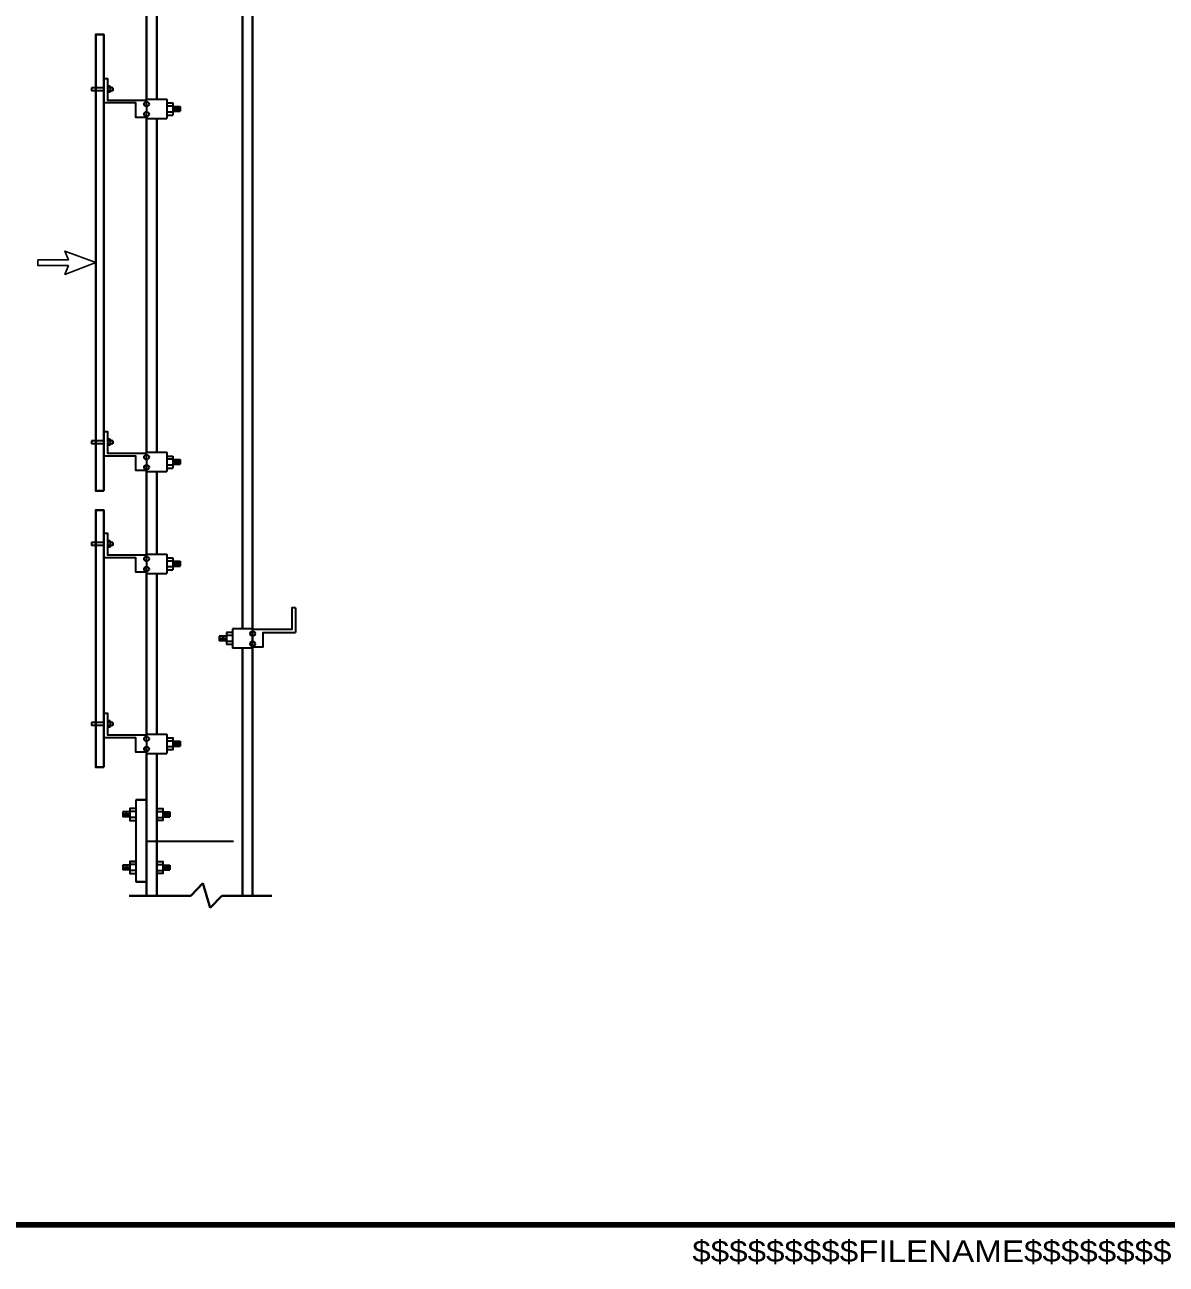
# Model space of a CAD drawing. Extents: x 851 to 1706, y -23 to 521.
# Drawn here: x 1358.6 to 1475.1, y -15.9 to 110.6 of the extents above; entities that cross this region are included whole.
import ezdxf

# ---------------------------------------------------------------- set-up
doc = ezdxf.new("R2010")
doc.units = 0
doc.header["$PDMODE"] = 32
doc.header["$PDSIZE"] = 0.5
doc.layers.add('1', color=7, linetype='Continuous', lineweight=35)

msp = doc.modelspace()

# ---------------------------------------------------------------- linework, layer by layer
at = {"layer": '1', "lineweight": 40}
for p, q in [((1381.875, 128.673), (1381.875, 21.729)), ((1380.841, 119.132), (1380.841, 48.984)), ((1371.049, 112.954), (1371.049, 103.03)), ((1372.082, 112.954), (1372.082, 103.03)), ((1371.049, 101.062), (1371.049, 66.999)), ((1372.082, 101.062), (1372.082, 66.999)), ((1371.049, 65.031), (1371.049, 56.611)), ((1372.082, 65.031), (1372.082, 56.611)), ((1371.049, 54.643), (1371.049, 38.241)), ((1372.082, 54.643), (1372.082, 38.241)), ((1380.841, 47.016), (1380.841, 21.729)), ((1371.049, 21.729), (1371.049, 36.272)), ((1372.082, 21.729), (1372.082, 36.272)), ((1371.049, 31.516), (1369.966, 31.516)), ((1371.049, 23.15), (1369.966, 23.15)), ((1376.79, 23.014), (1375.576, 21.729)), ((1376.79, 23.014), (1377.544, 20.498)), ((1369.278, 21.729), (1375.576, 21.729)), ((1378.726, 21.729), (1377.544, 20.498)), ((1378.726, 21.729), (1383.843, 21.729))]:
    msp.add_line(p, q, dxfattribs=at)
at = {"layer": '1'}
for p, q in [((1366.686, 105.163), (1366.686, 102.648)), ((1365.425, 104.206), (1365.425, 103.905)), ((1366.686, 104.206), (1365.425, 104.206)), ((1366.686, 103.905), (1365.425, 103.905)), ((1367.342, 104.37), (1367.047, 104.37)), ((1367.604, 104.206), (1367.047, 104.206)), ((1367.604, 103.905), (1367.047, 103.905)), ((1367.342, 103.741), (1367.047, 103.741)), ((1367.342, 104.37), (1367.342, 103.741)), ((1367.604, 104.206), (1367.604, 103.905)), ((1371.049, 103.03), (1373.116, 103.03)), ((1371.049, 102.347), (1371.049, 103.03)), ((1373.116, 103.03), (1373.116, 101.062)), ((1373.116, 102.648), (1373.726, 102.648)), ((1373.726, 102.648), (1373.726, 101.418)), ((1371.049, 102.347), (1371.049, 101.746)), ((1371.049, 101.308), (1371.049, 101.746)), ((1371.049, 101.308), (1371.049, 101.062)), ((1373.116, 102.347), (1373.726, 102.347)), ((1373.116, 101.746), (1373.726, 101.746)), ((1373.116, 101.418), (1373.726, 101.418)), ((1373.726, 102.292), (1374.461, 102.292)), ((1373.726, 101.8), (1374.461, 101.8)), ((1373.918, 102.156), (1373.918, 101.91)), ((1374.097, 102.292), (1374.097, 101.8)), ((1374.297, 102.156), (1374.297, 101.91)), ((1374.461, 102.292), (1374.461, 101.8)), ((1371.049, 101.062), (1373.116, 101.062)), ((1366.686, 69.132), (1366.686, 66.617)), ((1367.342, 68.339), (1367.047, 68.339)), ((1367.342, 68.339), (1367.342, 67.71)), ((1365.425, 68.175), (1365.425, 67.874)), ((1366.686, 68.175), (1365.425, 68.175)), ((1366.686, 67.874), (1365.425, 67.874)), ((1367.604, 68.175), (1367.047, 68.175)), ((1367.604, 67.874), (1367.047, 67.874)), ((1367.342, 67.71), (1367.047, 67.71)), ((1367.604, 68.175), (1367.604, 67.874)), ((1371.049, 67), (1373.116, 67)), ((1371.049, 66.316), (1371.049, 67)), ((1371.049, 66.316), (1371.049, 65.715)), ((1373.116, 67), (1373.116, 65.031)), ((1373.116, 66.617), (1373.726, 66.617)), ((1373.116, 66.316), (1373.726, 66.316)), ((1373.726, 66.617), (1373.726, 65.387)), ((1373.726, 66.261), (1374.461, 66.261)), ((1373.918, 66.125), (1373.918, 65.879)), ((1374.097, 66.261), (1374.097, 65.769)), ((1374.297, 66.125), (1374.297, 65.879)), ((1374.461, 66.261), (1374.461, 65.769)), ((1371.049, 65.277), (1371.049, 65.715)), ((1371.049, 65.277), (1371.049, 65.031)), ((1371.049, 65.031), (1373.116, 65.031)), ((1373.116, 65.715), (1373.726, 65.715)), ((1373.116, 65.387), (1373.726, 65.387)), ((1373.726, 65.769), (1374.461, 65.769)), ((1366.686, 58.744), (1366.686, 56.229)), ((1365.425, 57.787), (1365.425, 57.486)), ((1366.686, 57.787), (1365.425, 57.787)), ((1366.686, 57.486), (1365.425, 57.486)), ((1367.342, 57.951), (1367.047, 57.951)), ((1367.604, 57.787), (1367.047, 57.787)), ((1367.604, 57.486), (1367.047, 57.486)), ((1367.342, 57.322), (1367.047, 57.322)), ((1367.342, 57.951), (1367.342, 57.322)), ((1367.604, 57.787), (1367.604, 57.486)), ((1371.049, 56.611), (1373.116, 56.611)), ((1371.049, 55.928), (1371.049, 56.611)), ((1371.049, 55.928), (1371.049, 55.327)), ((1373.116, 56.611), (1373.116, 54.643)), ((1373.116, 56.229), (1373.726, 56.229)), ((1373.116, 55.928), (1373.726, 55.928)), ((1373.726, 56.229), (1373.726, 54.998)), ((1373.726, 55.873), (1374.461, 55.873)), ((1373.918, 55.736), (1373.918, 55.491)), ((1374.097, 55.873), (1374.097, 55.381)), ((1374.297, 55.736), (1374.297, 55.491)), ((1374.461, 55.873), (1374.461, 55.381)), ((1371.049, 54.889), (1371.049, 55.327)), ((1371.049, 54.889), (1371.049, 54.643)), ((1371.049, 54.643), (1373.116, 54.643)), ((1373.116, 55.327), (1373.726, 55.327)), ((1373.116, 54.998), (1373.726, 54.998)), ((1373.726, 55.381), (1374.461, 55.381)), ((1386.238, 51.116), (1386.238, 48.601)), ((1379.197, 48.246), (1378.463, 48.246)), ((1378.463, 48.246), (1378.463, 47.754)), ((1378.627, 48.109), (1378.627, 47.863)), ((1378.827, 48.246), (1378.827, 47.754)), ((1379.005, 48.109), (1379.005, 47.863)), ((1379.808, 48.601), (1379.197, 48.601)), ((1379.197, 48.601), (1379.197, 47.371)), ((1379.808, 48.301), (1379.197, 48.301)), ((1381.875, 48.984), (1379.808, 48.984)), ((1379.808, 48.984), (1379.808, 47.016)), ((1381.875, 48.301), (1381.875, 48.984)), ((1381.875, 48.301), (1381.875, 47.699)), ((1379.197, 47.754), (1378.463, 47.754)), ((1379.808, 47.699), (1379.197, 47.699)), ((1379.808, 47.371), (1379.197, 47.371)), ((1381.875, 47.016), (1379.808, 47.016)), ((1381.875, 47.262), (1381.875, 47.699)), ((1381.875, 47.262), (1381.875, 47.016)), ((1365.425, 39.416), (1365.425, 39.115)), ((1366.686, 39.416), (1365.425, 39.416)), ((1366.686, 40.373), (1366.686, 37.858)), ((1367.342, 39.58), (1367.047, 39.58)), ((1367.604, 39.416), (1367.047, 39.416)), ((1367.342, 39.58), (1367.342, 38.951)), ((1367.604, 39.416), (1367.604, 39.115)), ((1366.686, 39.115), (1365.425, 39.115)), ((1367.604, 39.115), (1367.047, 39.115)), ((1367.342, 38.951), (1367.047, 38.951)), ((1371.049, 38.241), (1373.116, 38.241)), ((1371.049, 37.557), (1371.049, 38.241)), ((1373.116, 38.241), (1373.116, 36.272)), ((1371.049, 37.557), (1371.049, 36.956)), ((1371.049, 36.518), (1371.049, 36.956)), ((1373.116, 37.557), (1373.726, 37.557)), ((1373.116, 36.956), (1373.726, 36.956)), ((1373.726, 37.502), (1374.461, 37.502)), ((1373.726, 37.01), (1374.461, 37.01)), ((1373.918, 37.366), (1373.918, 37.12)), ((1374.097, 37.502), (1374.097, 37.01)), ((1374.297, 37.366), (1374.297, 37.12)), ((1374.461, 37.502), (1374.461, 37.01)), ((1371.049, 36.518), (1371.049, 36.272)), ((1371.049, 36.272), (1373.116, 36.272)), ((1369.966, 31.516), (1369.966, 23.15)), ((1369.356, 30.287), (1368.615, 30.287)), ((1368.615, 30.287), (1368.615, 29.795)), ((1369.356, 29.795), (1368.615, 29.795)), ((1368.78, 30.151), (1368.78, 29.905)), ((1368.98, 30.287), (1368.98, 29.795)), ((1369.158, 30.151), (1369.158, 29.905)), ((1369.966, 30.347), (1369.356, 30.347)), ((1369.966, 29.732), (1369.356, 29.732)), ((1369.356, 29.424), (1369.966, 29.424)), ((1372.082, 30.347), (1372.693, 30.347)), ((1372.082, 29.732), (1372.693, 29.732)), ((1372.693, 29.424), (1372.082, 29.424)), ((1372.693, 30.287), (1373.434, 30.287)), ((1372.693, 29.795), (1373.434, 29.795)), ((1372.891, 30.151), (1372.891, 29.905)), ((1373.07, 30.287), (1373.07, 29.795)), ((1373.269, 30.151), (1373.269, 29.905)), ((1373.434, 30.287), (1373.434, 29.795)), ((1371.049, 27.306), (1379.933, 27.306)), ((1369.356, 24.865), (1368.621, 24.865)), ((1368.621, 24.865), (1368.621, 24.373)), ((1369.356, 24.373), (1368.621, 24.373)), ((1368.785, 24.728), (1368.785, 24.482)), ((1368.985, 24.865), (1368.985, 24.373)), ((1369.163, 24.728), (1369.163, 24.482)), ((1369.356, 25.242), (1369.966, 25.242)), ((1369.966, 24.934), (1369.356, 24.934)), ((1369.966, 24.319), (1369.356, 24.319)), ((1372.082, 24.934), (1372.693, 24.934)), ((1372.082, 24.319), (1372.693, 24.319)), ((1372.693, 24.865), (1373.428, 24.865)), ((1372.693, 24.373), (1373.428, 24.373)), ((1372.886, 24.728), (1372.886, 24.482)), ((1373.064, 24.865), (1373.064, 24.373)), ((1373.264, 24.728), (1373.264, 24.482)), ((1373.428, 24.865), (1373.428, 24.373))]:
    msp.add_line(p, q, dxfattribs=at)
at = {"layer": '1', "lineweight": 25}
for q in [(1385.844, 51.116), (1386.238, 48.601)]:
    msp.add_line((1386.238, 51.116), q, dxfattribs=at)
at = {"layer": '1', "lineweight": 158}
msp.add_line((1699.744, -11.848), (908.144, -11.848), dxfattribs=at)
at = {"layer": '1', "lineweight": 40}
for points in [[(1366.686, 63.063), (1366.686, 109.646), (1365.856, 109.646), (1365.856, 63.063)], [(1366.686, 34.851), (1366.686, 61.095), (1365.856, 61.095), (1365.856, 34.851)]]:
    msp.add_lwpolyline(points, close=True, dxfattribs=at)
at = {"layer": '1', "lineweight": 25}
for points in [[(1366.686, 105.163), (1367.047, 105.163), (1367.047, 102.948)], [(1366.686, 69.132), (1367.047, 69.132), (1367.047, 66.918)], [(1366.686, 58.744), (1367.047, 58.744), (1367.047, 56.529)], [(1366.686, 58.744), (1367.047, 58.744), (1367.047, 56.529)], [(1366.686, 40.373), (1367.047, 40.373), (1367.047, 38.159)]]:
    msp.add_lwpolyline(points, dxfattribs=at)
at = {"layer": '1'}
for points in [[(1366.686, 105.163), (1367.047, 105.163), (1367.047, 102.948), (1371.049, 102.948)], [(1371.049, 101.172), (1369.966, 101.172), (1369.966, 102.648), (1366.686, 102.648)], [(1366.686, 69.132), (1367.047, 69.132), (1367.047, 66.918), (1371.049, 66.918)], [(1371.049, 65.141), (1369.966, 65.141), (1369.966, 66.617), (1366.686, 66.617)], [(1366.686, 58.744), (1367.047, 58.744), (1367.047, 56.529), (1371.049, 56.529)], [(1371.049, 54.752), (1369.966, 54.752), (1369.966, 56.229), (1366.686, 56.229)], [(1386.238, 51.116), (1385.877, 51.116), (1385.877, 48.902), (1381.875, 48.902)], [(1381.875, 47.125), (1382.957, 47.125), (1382.957, 48.601), (1386.238, 48.601)], [(1366.686, 40.373), (1367.047, 40.373), (1367.047, 38.159), (1371.049, 38.159)], [(1371.049, 36.382), (1369.966, 36.382), (1369.966, 37.858), (1366.686, 37.858)], [(1373.116, 37.858), (1373.726, 37.858), (1373.726, 36.628), (1373.116, 36.628)], [(1369.966, 30.654), (1369.356, 30.654), (1369.356, 29.424), (1369.966, 29.424)], [(1372.082, 30.654), (1372.693, 30.654), (1372.693, 29.424), (1372.082, 29.424)], [(1369.966, 25.242), (1369.356, 25.242), (1369.356, 24.011), (1369.966, 24.011)], [(1372.082, 25.242), (1372.693, 25.242), (1372.693, 24.011), (1372.082, 24.011)]]:
    msp.add_lwpolyline(points, dxfattribs=at)
at = {"layer": '1', "lineweight": 25}
msp.add_lwpolyline([(1363.068, 86.054), (1359.951, 86.054), (1359.951, 86.628), (1363.068, 86.628), (1362.712, 87.53), (1365.856, 86.354), (1362.712, 85.152)], close=True, dxfattribs=at)
msp.add_lwpolyline([(1363.068, 86.054), (1359.951, 86.054), (1359.951, 86.628), (1363.068, 86.628), (1362.712, 87.53), (1365.856, 86.354), (1362.712, 85.152)], close=True, dxfattribs=at)
at = {"layer": '1'}
for p in [(1371.049, 102.538), (1371.049, 101.5), (1371.049, 66.508), (1371.049, 65.469), (1371.049, 56.119), (1371.049, 55.08), (1381.875, 48.492), (1381.875, 47.453), (1371.049, 37.748), (1371.049, 36.71)]:
    msp.add_point(p, dxfattribs=at)

# ---------------------------------------------------------------- texts
at = {"layer": '1', "width": 1.15}
msp.add_text('$$$$$$$$$FILENAME$$$$$$$$', height=2.2, dxfattribs=at).set_placement((1426.744, -15.648))

doc.saveas('drawing.dxf')
